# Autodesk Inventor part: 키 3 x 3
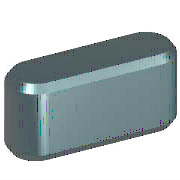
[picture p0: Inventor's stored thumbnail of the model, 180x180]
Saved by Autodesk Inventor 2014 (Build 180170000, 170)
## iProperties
Created: 2012-02
Part Number: 키 3 x 3
Material: 강철, 연강
Description: 키 및 해당 키홈
Document SubType Name: Modeling
Standard: KS B 1311
Designer: mduedu
Standards Organization: KS
Language: ko-KR
Size Designation: 3 x 3 x 12
Categories: <MemberInstance><Categories><Category DisplayName="샤프트 부품" InternalName="7f7aeb1f-a693-4053-b835-cee3144e0d98" Mnemonic="SHFT"><Category DisplayName="키" Interna
Density: 7.86 g/cm^3
Mass: 0.790122 g
Surface Area: 1.42216 cm^2
Volume: 0.100524 cm^3
Appearance: 노란색
IsCustomPart: 1
Author: mduedu
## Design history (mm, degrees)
workplane "Work Plane1"
workplane "Work Plane2"
sketch "스케치1"
  geometry: L1 (1.5, 1.5)-(10.5, 1.5); L2 (10.5, -1.5)-(1.5, -1.5); L3 (0, 9.4)-(0, -7.4) reference; L4 (-5, 0)-(30, 0) reference; L5 (12, 0)-(12, 7); A1 r 1.5 centre (1.5, 0) between (1.5, 1.5) and (1.5, -1.5); A2 r 1.5 centre (10.5, 0) between (10.5, -1.5) and (10.5, 1.5)
  constraints: 6 end point, 5 point on circle, 4 tangent, 3 point on line, 2 centre point, 1 horizontal, 1 parallel, 1 perpendicular
  dimensions: "d0" = 1.5 radius of A1 (= 0.5 x PB); "d13" = 1.5 radius of A2 (= 0.5 x PB); "d14" = 12 distance between parallel lines of L5 L3 (= NLG)
extrude "본체1" new body sketch "스케치1" taper "d3" = 0 deg; stored distance "d4" = 10
workplane "Work Plane3"
body "Solid1"
chamfer "모따기1" distance "d8" = 0.25 (= PHH); stored, may be unused: second distance "d9" = 0.25 (= PHH), angle "d15" = 45 deg
other parameters: "d1" = -1.8 (= -PNT), "d2" = 1.2 (= PH - PNT), "NLG" = 12 [user parameter; used in 3 equation terms], "PB" = 3 [user parameter; used in 2 equation terms], "PNT" = 1.8 [user parameter; used in 2 equation terms], "PH" = 3 [user parameter; used in 1 equation term], "PHH" = 0.25 [user parameter; used in 2 equation terms], "d10" = 0, "d16" = 0, "d17" = 0, "d18" = 0, "WDMIN" = 8 [user parameter], "PLB2" = 12 (= NLG) [user parameter], "PLB1" = 12 (= NLG) [user parameter], "RR" = 0.08 [user parameter], "PUEB" = 1.4 [user parameter]
